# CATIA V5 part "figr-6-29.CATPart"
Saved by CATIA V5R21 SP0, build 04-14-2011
Part number: Part1
Bounding box of the stored display mesh (mm): x -61 to 61, y 0 to 173.636, z 0 to 130.49
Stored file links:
  D:\CATIA V5R21 E-RESOURCES\CATIA-V5R21\catia-v5r21-prt\c06-catia-v5r21-prt\c06-catia-v5r21-figr-6-29.CATPart
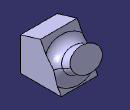
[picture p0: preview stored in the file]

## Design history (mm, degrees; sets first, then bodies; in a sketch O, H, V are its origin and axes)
Body1 (main body)
  Sketch1 on yz-plane, origin (0, 0, 0), H (0, 1, 0), V (0, 0, 1)
    line L1 (0, 0) -> (0, 110.5903)
    line L2 (0, 110.5903) -> (66.2814, 130.4899)
    line L3 (66.2814, 130.4899) -> (135.1646, 0)
    point P3 (135.1646, 0)
    line L4 (135.1646, 0) -> (0, 0)
    vertical: L1 V
    coincidence: P3 H
    horizontal: L4 H
  Pad1: profile Sketch1, direction (1, 0, 0), length 61, mirrored extent
  Sketch2 on face of Pad1, origin (0, 105.7081, 55.8014), H (-1, 0, 0), V (0, -0.4668, 0.8843)
    point P1 (0, 4.9672)
    ellipse A1 centre (0, 4.9672) semi-axes 50.9663, 34.9201 rotation 0
    coincidence: P1 V
  Pad2: profile Sketch2, direction (0, 0.8843, 0.4668), length 61
  Fillet1: radius 29, on edge [face of Pad1 | face of Pad2]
